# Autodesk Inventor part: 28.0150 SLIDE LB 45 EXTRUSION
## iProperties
Created: 2007-06
Part Number: 28.0150 SLIDE LB 45 EXTRUSION
Material: Aluminum-6061
Document SubType Name: Modeling
Designer: Andy Moles
Density: 2.71 g/cm^3
Author: Andy Moles
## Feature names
1. Extrusion1
2. Extrusion2
